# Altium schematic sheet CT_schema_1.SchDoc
size 515 x 464 mm
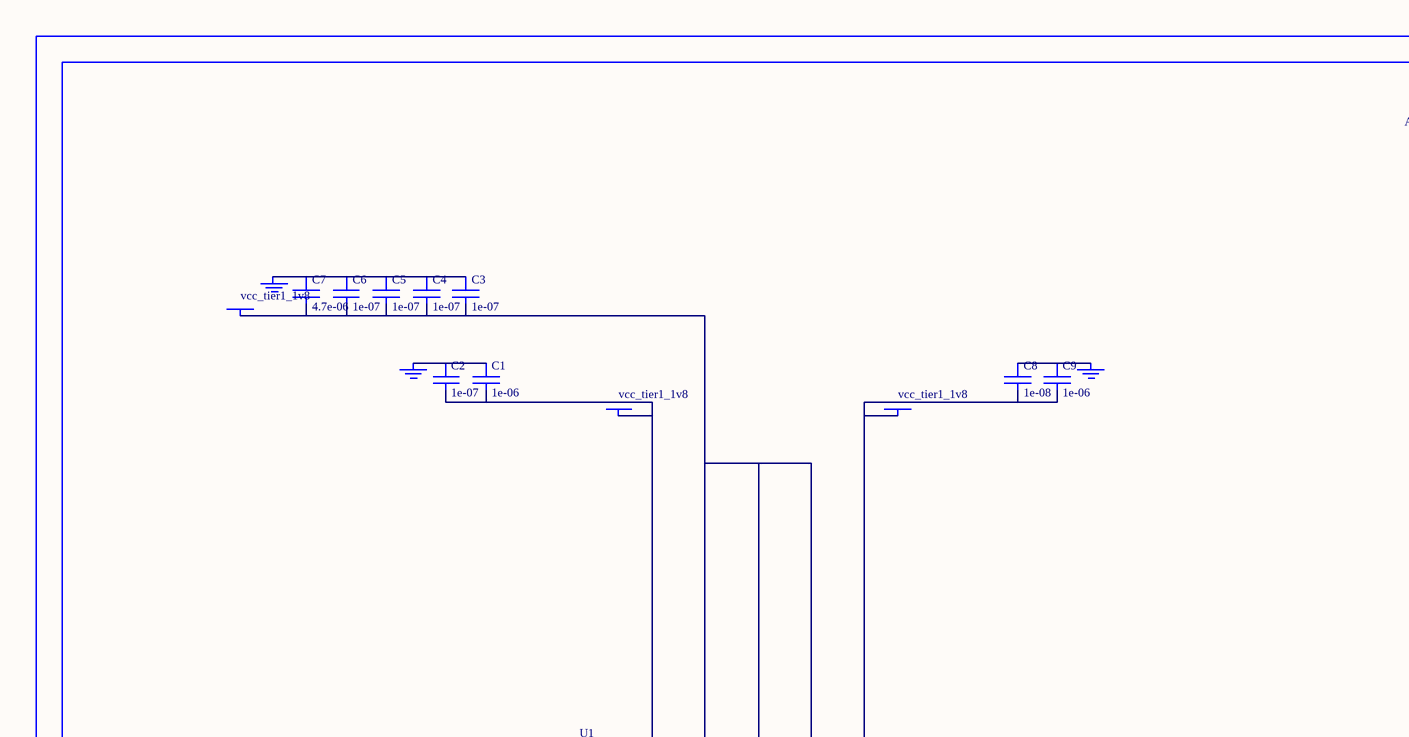
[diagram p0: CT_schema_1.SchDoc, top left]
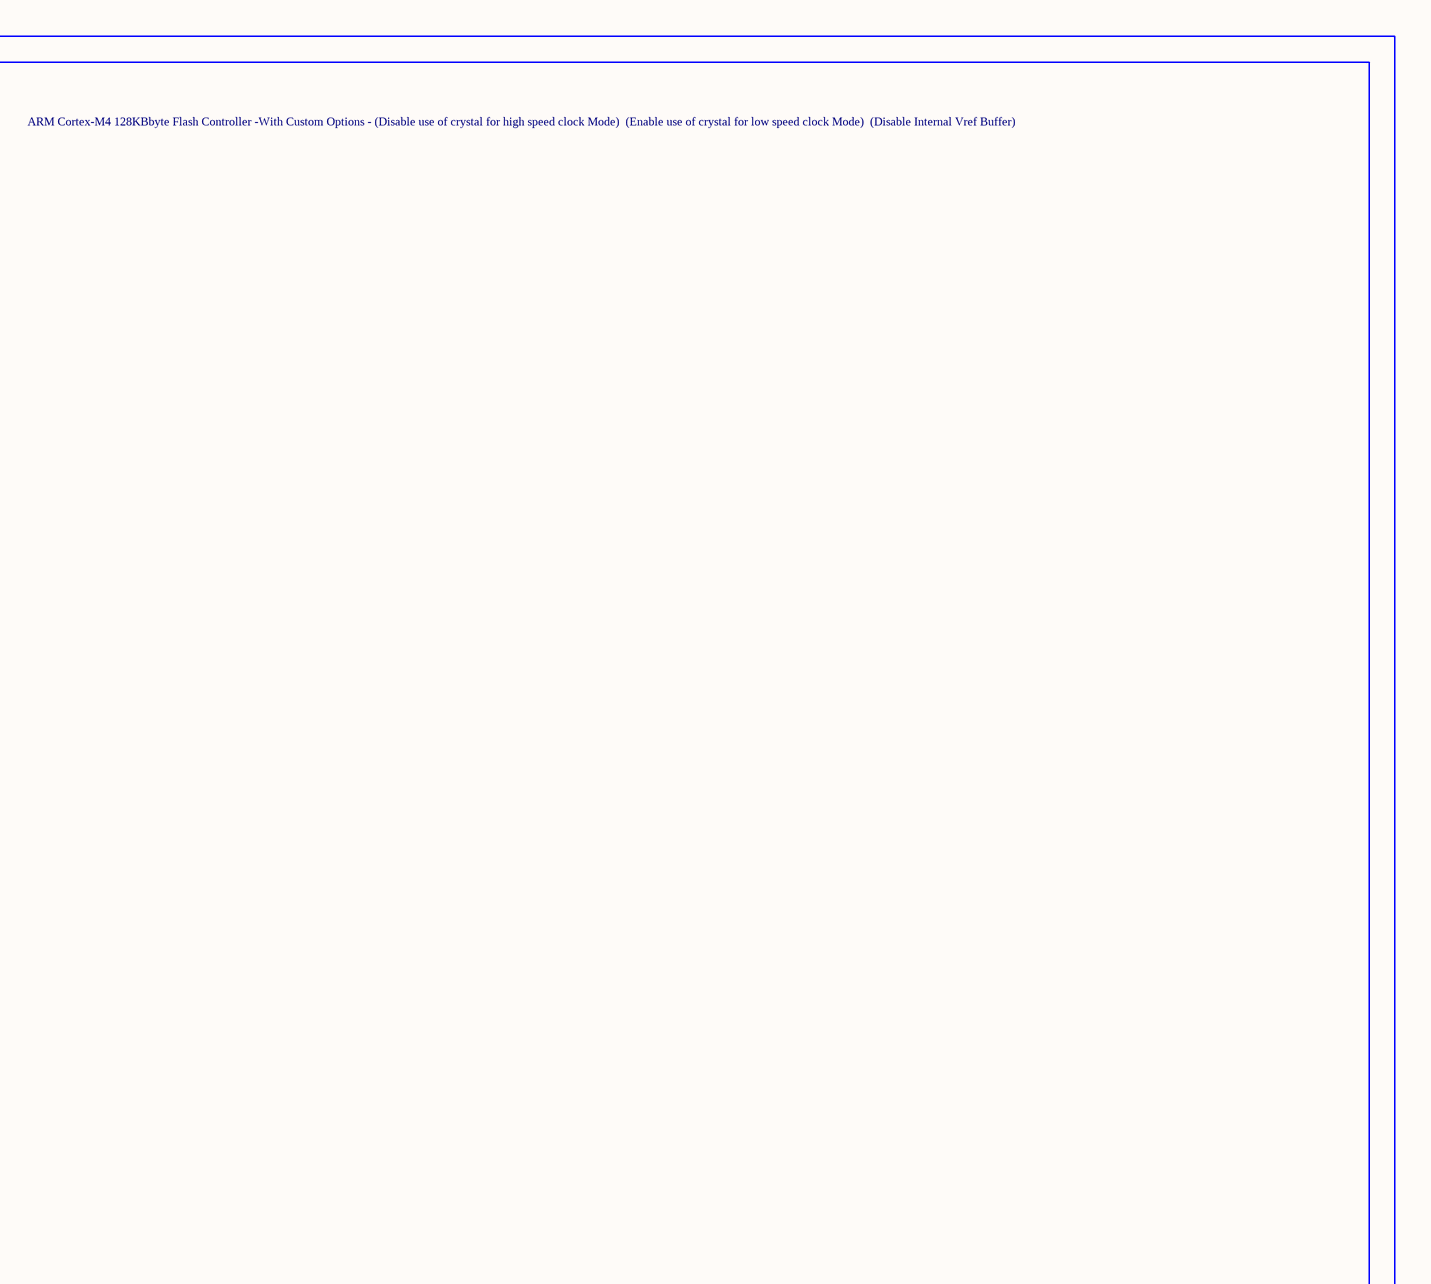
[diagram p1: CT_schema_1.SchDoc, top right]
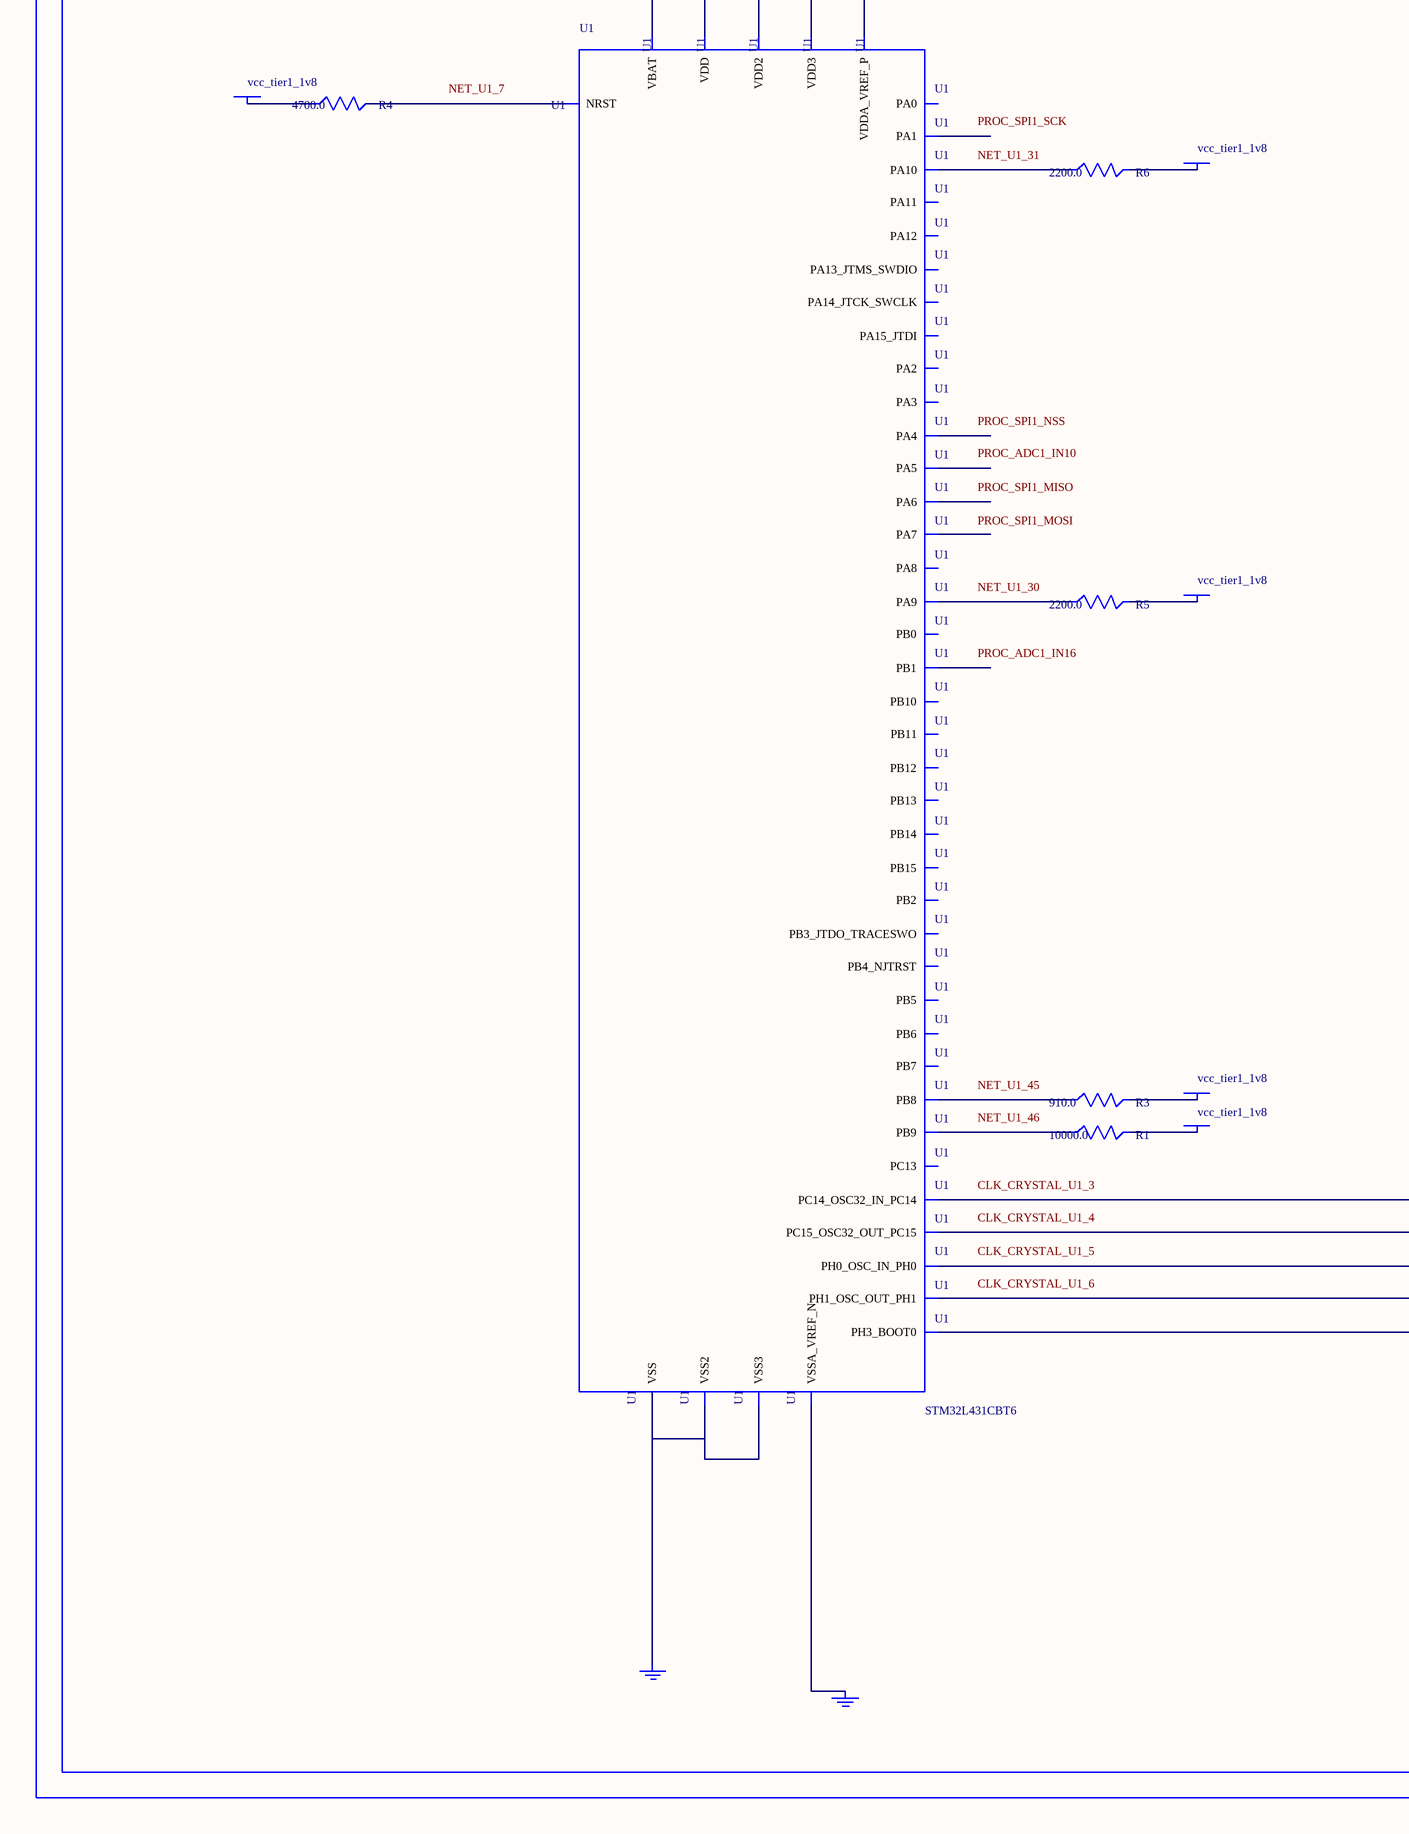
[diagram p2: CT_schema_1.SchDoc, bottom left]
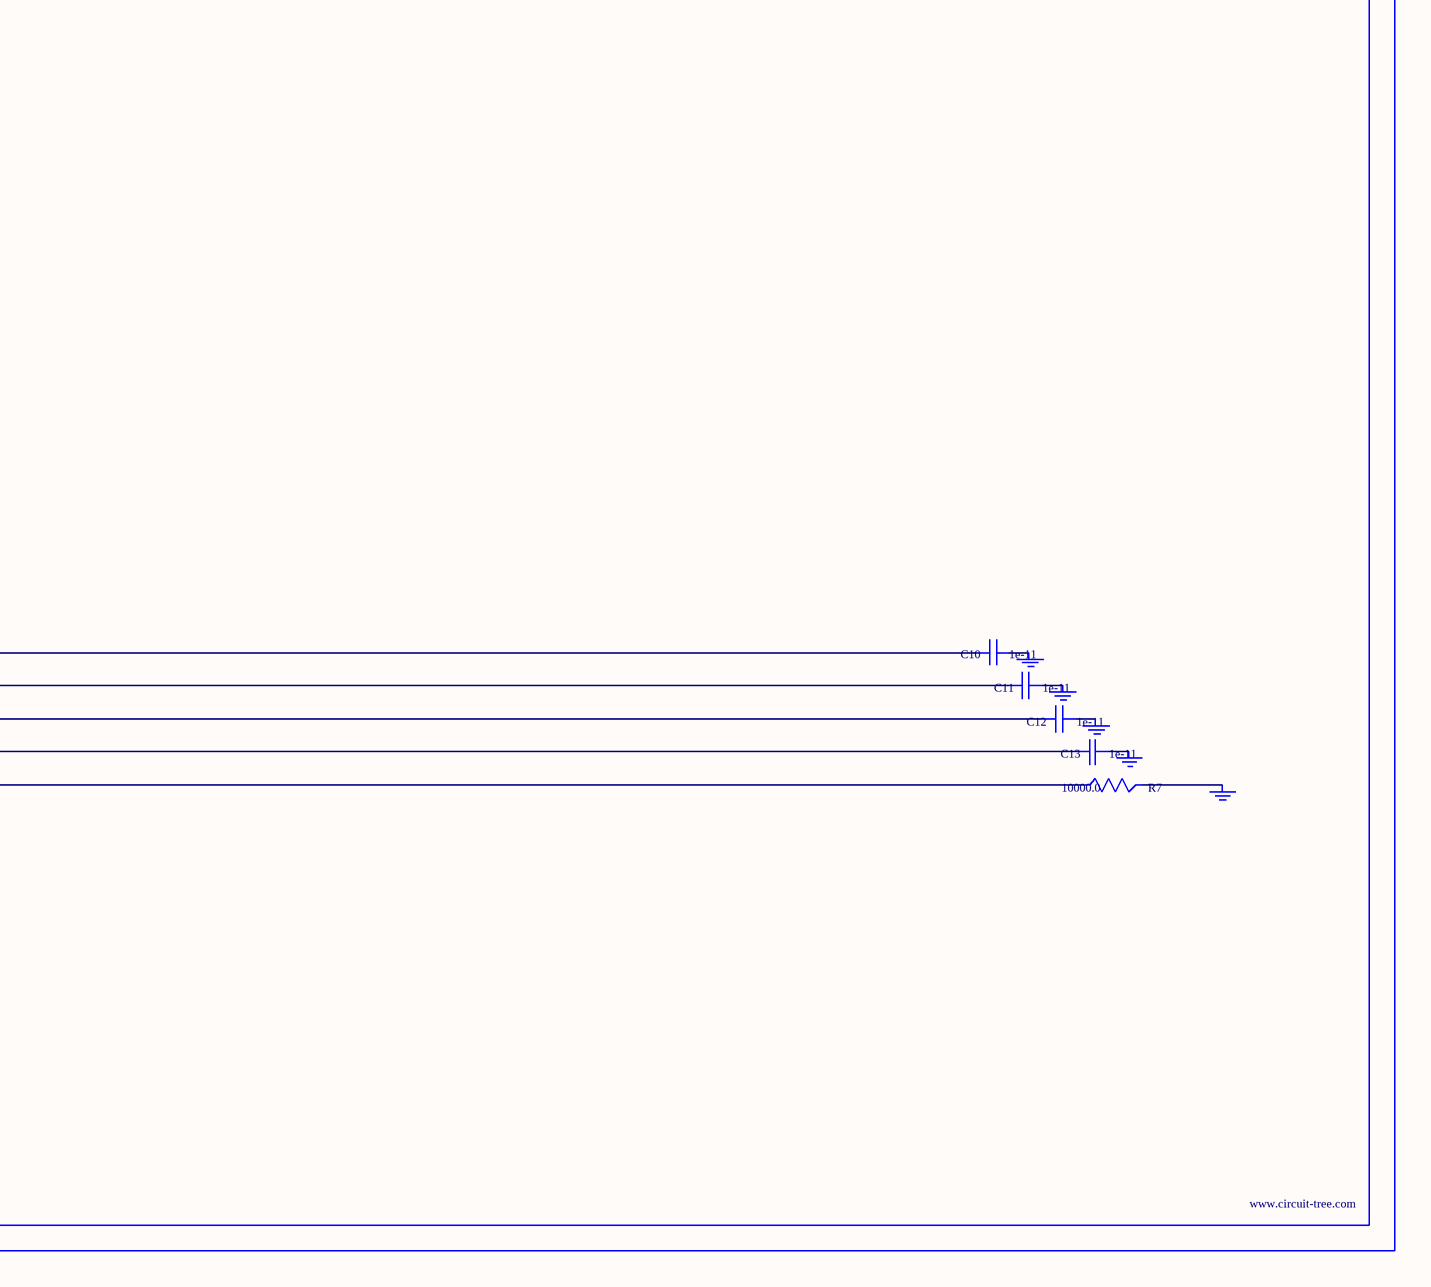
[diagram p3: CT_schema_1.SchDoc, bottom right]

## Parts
BORDER0  (no value)
C1  1e-06  [C0603]
C2  1e-07  [C0603]
C3  1e-07  [C0603]
C4  1e-07  [C0603]
C5  1e-07  [C0603]
C6  1e-07  [C0603]
C7  4.7e-06  [C0603]
C8  1e-08  [C0603]
C9  1e-06  [C0603]
C10  1e-11  [C0402]
C11  1e-11  [C0402]
C12  1e-11  [C0402]
C13  1e-11  [C0402]
GND_INSTANCE_0_0  (no value)
GND_INSTANCE_0_1  (no value)
GND_INSTANCE_0_2  (no value)
GND_INSTANCE_0_3  (no value)
GND_INSTANCE_0_4  (no value)
GND_INSTANCE_0_5  (no value)
GND_INSTANCE_0_6  (no value)
GND_INSTANCE_0_7  (no value)
GND_INSTANCE_0_8  (no value)
GND_INSTANCE_0_9  (no value)
POWER_INSTANCE_0_0  vcc_tier1_1v8
POWER_INSTANCE_0_1  vcc_tier1_1v8
POWER_INSTANCE_0_2  vcc_tier1_1v8
POWER_INSTANCE_0_3  vcc_tier1_1v8
POWER_INSTANCE_0_4  vcc_tier1_1v8
POWER_INSTANCE_0_5  vcc_tier1_1v8
POWER_INSTANCE_0_6  vcc_tier1_1v8
POWER_INSTANCE_0_7  vcc_tier1_1v8
R1  10000.0  [R0603]
R3  910.0  [R0603]
R4  4700.0  [R0603]
R5  2200.0  [R0603]
R6  2200.0  [R0603]
R7  10000.0  [R0603]
U1  STM32L431CBT6  [LQFP48]

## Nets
NetC1_1: C1.1 C2.1 GND_INSTANCE_0_0.0(GND)
NetC1_2: C1.2 C2.2 POWER_INSTANCE_0_0.0(PWR) U1.1(VBAT)
NetC3_1: C3.1 C4.1 C5.1 C6.1 C7.1 GND_INSTANCE_0_7.0(GND)
NetC3_2: C3.2 C4.2 C5.2 C6.2 C7.2 POWER_INSTANCE_0_2.0(PWR) U1.24(VDD) U1.36(VDD2) U1.48(VDD3)
NetC8_1: C8.1 C9.1 GND_INSTANCE_0_6.0(GND)
NetC8_2: C8.2 C9.2 POWER_INSTANCE_0_1.0(PWR) U1.9(VDDA_VREF_P)
NetC10_1: C10.1 GND_INSTANCE_0_1.0(GND)
NetC10_2: C10.2 U1.3(PC14_OSC32_IN_PC14)
NetC11_1: C11.1 GND_INSTANCE_0_2.0(GND)
NetC11_2: C11.2 U1.4(PC15_OSC32_OUT_PC15)
NetC12_1: C12.1 GND_INSTANCE_0_3.0(GND)
NetC12_2: C12.2 U1.5(PH0_OSC_IN_PH0)
NetC13_1: C13.1 GND_INSTANCE_0_4.0(GND)
NetC13_2: C13.2 U1.6(PH1_OSC_OUT_PH1)
NetGND_INSTANCE_0_5_0: GND_INSTANCE_0_5.0(GND) U1.8(VSSA_VREF_N)
NetGND_INSTANCE_0_8_0: GND_INSTANCE_0_8.0(GND) R7.2
NetGND_INSTANCE_0_9_0: GND_INSTANCE_0_9.0(GND) U1.23(VSS) U1.35(VSS2) U1.47(VSS3)
NetPOWER_INSTANCE_0_3_0: POWER_INSTANCE_0_3.0(PWR) R4.1
NetPOWER_INSTANCE_0_4_0: POWER_INSTANCE_0_4.0(PWR) R5.2
NetPOWER_INSTANCE_0_5_0: POWER_INSTANCE_0_5.0(PWR) R6.2
NetPOWER_INSTANCE_0_6_0: POWER_INSTANCE_0_6.0(PWR) R3.2
NetPOWER_INSTANCE_0_7_0: POWER_INSTANCE_0_7.0(PWR) R1.2
NetR1_1: R1.1 U1.46(PB9)
NetR3_1: R3.1 U1.45(PB8)
NetR4_2: R4.2 U1.7(NRST)
NetR5_1: R5.1 U1.30(PA9)
NetR6_1: R6.1 U1.31(PA10)
NetR7_1: R7.1 U1.44(PH3_BOOT0)

Not connected (* = marked no-connect by the designer): U1 2(PC13) 10(PA0) 11(PA1) 12(PA2) 13(PA3) 14(PA4) 15(PA5) 16(PA6) 17(PA7) 18(PB0) 19(PB1) 20(PB2) 21(PB10) 22(PB11) 25(PB12) 26(PB13) 27(PB14) 28(PB15) 29(PA8) 32(PA11) 33(PA12) 34(PA13_JTMS_SWDIO) 37(PA14_JTCK_SWCLK) 38(PA15_JTDI) 39(PB3_JTDO_TRACESWO) 40(PB4_NJTRST) 41(PB5) 42(PB6) 43(PB7)

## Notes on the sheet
- Labels drawn without touching a wire or pin: CLK_CRYSTAL_U1_3, CLK_CRYSTAL_U1_4, CLK_CRYSTAL_U1_5, CLK_CRYSTAL_U1_6, NET_U1_7, NET_U1_30, NET_U1_31, NET_U1_45, NET_U1_46, PROC_ADC1_IN10, PROC_ADC1_IN16, PROC_SPI1_MISO, PROC_SPI1_MOSI, PROC_SPI1_NSS, PROC_SPI1_SCK

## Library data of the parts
BORDER0 = BORDER_PAGE0
C1 C9 = C0603C105K3RACTU
C2-C6 = 06035C104K4Z2A
C7 = GRM188R6YA475KE15D
C8 = 06035C103K4Z2A
C10-C13 = C0402C100K3GACTU
GND_INSTANCE_0_0-GND_INSTANCE_0_9 = GND
POWER_INSTANCE_0_0-POWER_INSTANCE_0_7 = PWR
R1 R7 = RC0603JR-0710KL
R3 = RC0603JR-07910RL
R4 = RC0603JR-074K7L
R5 R6 = RC0603JR-072K2L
